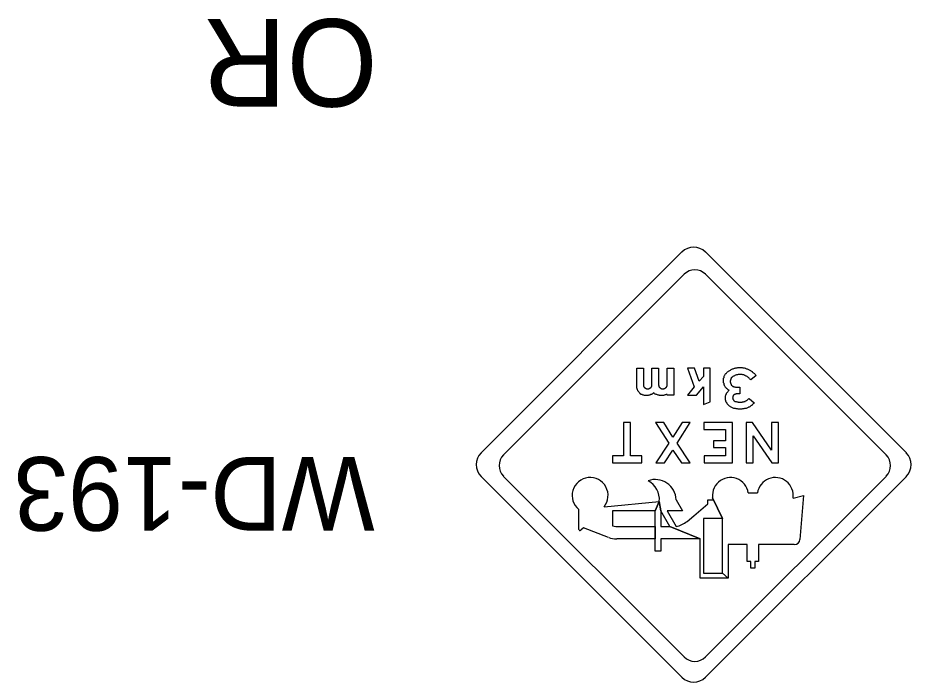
# Model space of a CAD drawing. Extents: x 1342 to 1558, y 178 to 457.
# Drawn here: x 1372.24 to 1398.65, y 386.57 to 406.21 of the extents above; entities that cross this region are included whole.
import ezdxf

# ---------------------------------------------------------------- set-up
doc = ezdxf.new("R2010")
doc.units = 0
for name, color, linetype in [('Level 1', 7, 'Continuous'), ('Level 10', 7, 'Continuous'), ('Level 44', 7, 'Continuous')]:
    doc.layers.add(name, color=color, linetype=linetype)

msp = doc.modelspace()

# ---------------------------------------------------------------- linework, layer by layer
at = {"layer": 'Level 1'}
for p, q in [((1393.832, 392.165), (1394.107, 392.165)), ((1389.57, 391.756), (1391.202, 391.916)), ((1391.202, 391.916), (1391.083, 391.633)), ((1391.083, 391.633), (1391.202, 391.916)), ((1391.248, 391.633), (1391.202, 391.916)), ((1391.202, 391.916), (1391.248, 391.633)), ((1391.703, 391.965), (1391.887, 391.633)), ((1392.642, 391.842), (1392.642, 391.965)), ((1392.642, 391.965), (1392.79, 391.965)), ((1393.076, 391.409), (1392.78, 392.016)), ((1392.78, 392.016), (1393.076, 391.409)), ((1395.158, 392.012), (1395.463, 392.09)), ((1395.463, 392.09), (1395.36, 390.791)), ((1388.826, 391.089), (1388.826, 391.676)), ((1391.083, 391.633), (1389.821, 391.633)), ((1389.821, 391.633), (1389.821, 391.194)), ((1391.083, 391.169), (1391.083, 391.633)), ((1391.513, 391.174), (1391.248, 391.633)), ((1391.248, 391.633), (1391.248, 391.169)), ((1391.887, 391.633), (1391.44, 391.633)), ((1391.44, 391.633), (1391.702, 391.177)), ((1392.221, 391.489), (1392.642, 391.842)), ((1392.025, 391.325), (1392.221, 391.489)), ((1393.076, 391.409), (1392.515, 391.409)), ((1392.515, 391.409), (1392.515, 389.793)), ((1393.076, 389.793), (1393.076, 391.409)), ((1388.962, 391.131), (1388.88, 391.064)), ((1389.707, 390.848), (1388.962, 391.131)), ((1390.011, 391.169), (1391.083, 391.169)), ((1391.083, 391.169), (1391.083, 390.804)), ((1391.083, 390.804), (1391.083, 391.169)), ((1391.248, 391.169), (1391.516, 391.169)), ((1392.41, 390.804), (1391.513, 391.174)), ((1391.513, 391.174), (1392.41, 390.804)), ((1391.516, 391.169), (1391.513, 391.174)), ((1391.083, 390.804), (1389.944, 390.804)), ((1391.083, 390.445), (1391.083, 390.804)), ((1392.41, 390.804), (1391.248, 390.804)), ((1391.248, 390.804), (1391.248, 390.445)), ((1392.41, 389.643), (1392.41, 390.804)), ((1393.804, 390.638), (1393.24, 390.638)), ((1393.24, 390.638), (1393.24, 389.643)), ((1393.804, 390.14), (1393.804, 390.638)), ((1395.194, 390.638), (1394.135, 390.638)), ((1394.135, 390.638), (1394.135, 390.14)), ((1391.248, 390.445), (1391.083, 390.445)), ((1393.907, 390.14), (1393.804, 390.14)), ((1393.907, 389.937), (1393.907, 390.14)), ((1394.135, 390.14), (1394.029, 390.14)), ((1394.029, 390.14), (1394.029, 389.937)), ((1392.515, 389.793), (1393.076, 389.793)), ((1393.24, 389.643), (1393.076, 389.793)), ((1393.076, 389.793), (1393.24, 389.643)), ((1394.029, 389.937), (1393.907, 389.937)), ((1393.24, 389.643), (1392.41, 389.643))]:
    msp.add_line(p, q, dxfattribs=at)
for points in [[(1390.54, 395.296), (1390.54, 395.85), (1390.738, 395.85), (1390.738, 395.361)], [(1390.982, 395.361), (1390.982, 395.85), (1391.179, 395.85), (1391.179, 395.361)], [(1391.433, 395.361), (1391.433, 395.85), (1391.631, 395.85), (1391.631, 395.051), (1391.433, 395.051), (1391.433, 395.079)], [(1392.506, 394.778), (1392.703, 394.854), (1392.703, 395.85), (1392.506, 395.85), (1392.506, 395.606), (1392.383, 395.465), (1392.242, 395.85), (1392.035, 395.85), (1392.233, 395.305), (1392.035, 395.051), (1392.308, 395.051), (1392.506, 395.305), (1392.506, 394.778)], [(1393.267, 395.202), (1393.249, 395.202), (1393.239, 395.211), (1393.23, 395.22), (1393.22, 395.23), (1393.211, 395.239), (1393.192, 395.249), (1393.183, 395.267), (1393.173, 395.277), (1393.164, 395.286), (1393.164, 395.296), (1393.154, 395.305), (1393.145, 395.324), (1393.136, 395.333), (1393.136, 395.352), (1393.126, 395.361), (1393.117, 395.371), (1393.117, 395.39), (1393.117, 395.399), (1393.107, 395.418), (1393.107, 395.427), (1393.107, 395.446), (1393.107, 395.465), (1393.107, 395.474), (1393.107, 395.493), (1393.107, 395.502), (1393.107, 395.521), (1393.107, 395.531), (1393.107, 395.549), (1393.107, 395.559), (1393.117, 395.578), (1393.117, 395.587), (1393.126, 395.606), (1393.126, 395.615), (1393.136, 395.634), (1393.145, 395.643), (1393.145, 395.653), (1393.154, 395.672), (1393.164, 395.681), (1393.173, 395.691), (1393.183, 395.7), (1393.192, 395.709), (1393.201, 395.728), (1393.211, 395.738), (1393.22, 395.747), (1393.239, 395.756), (1393.249, 395.766), (1393.267, 395.775), (1393.286, 395.784), (1393.305, 395.794), (1393.314, 395.804), (1393.333, 395.813), (1393.352, 395.822), (1393.371, 395.832), (1393.39, 395.832), (1393.408, 395.841), (1393.427, 395.85), (1393.446, 395.85), (1393.465, 395.86), (1393.483, 395.86), (1393.502, 395.86), (1393.521, 395.87), (1393.54, 395.87), (1393.559, 395.87), (1393.577, 395.87), (1393.597, 395.87), (1393.615, 395.87), (1393.634, 395.87), (1393.653, 395.87), (1393.672, 395.86), (1393.69, 395.86), (1393.709, 395.86), (1393.738, 395.85), (1393.756, 395.85), (1393.766, 395.841), (1393.784, 395.832), (1393.804, 395.832), (1393.822, 395.822), (1393.841, 395.813), (1393.86, 395.804), (1393.879, 395.794), (1393.897, 395.784), (1393.907, 395.775), (1393.925, 395.766), (1393.945, 395.756), (1393.954, 395.747), (1393.973, 395.728), (1393.991, 395.719), (1394.001, 395.709), (1394.02, 395.691), (1394.029, 395.681), (1394.039, 395.663), (1394.057, 395.643), (1394.066, 395.634)], [(1393.361, 395.587), (1393.352, 395.578), (1393.342, 395.578), (1393.333, 395.568), (1393.333, 395.559), (1393.324, 395.549), (1393.314, 395.54), (1393.314, 395.531), (1393.314, 395.521), (1393.305, 395.512), (1393.305, 395.502), (1393.305, 395.493), (1393.295, 395.484), (1393.295, 395.474), (1393.295, 395.465), (1393.295, 395.456), (1393.295, 395.446), (1393.295, 395.437), (1393.305, 395.427), (1393.305, 395.418), (1393.305, 395.408), (1393.314, 395.399), (1393.314, 395.39), (1393.324, 395.38), (1393.324, 395.371), (1393.333, 395.361), (1393.333, 395.352), (1393.342, 395.352), (1393.352, 395.343), (1393.361, 395.333), (1393.371, 395.333), (1393.371, 395.324), (1393.38, 395.315), (1393.39, 395.315), (1393.399, 395.315), (1393.408, 395.305), (1393.418, 395.305), (1393.427, 395.305), (1393.436, 395.305), (1393.456, 395.296), (1393.465, 395.296)], [(1393.907, 395.512), (1393.897, 395.521), (1393.879, 395.531), (1393.869, 395.54), (1393.86, 395.559), (1393.85, 395.568), (1393.841, 395.578), (1393.822, 395.587), (1393.813, 395.597), (1393.804, 395.606), (1393.784, 395.615), (1393.775, 395.615), (1393.756, 395.625), (1393.747, 395.634), (1393.728, 395.634), (1393.718, 395.643), (1393.7, 395.653), (1393.681, 395.653), (1393.672, 395.653), (1393.653, 395.663), (1393.634, 395.663), (1393.625, 395.663), (1393.606, 395.663), (1393.587, 395.663), (1393.577, 395.663), (1393.559, 395.663), (1393.54, 395.663), (1393.531, 395.663), (1393.512, 395.653), (1393.502, 395.653), (1393.483, 395.653), (1393.465, 395.643), (1393.456, 395.643), (1393.436, 395.634), (1393.427, 395.625), (1393.408, 395.615), (1393.399, 395.615), (1393.38, 395.606), (1393.371, 395.597), (1393.361, 395.587)], [(1394.066, 395.634), (1393.907, 395.512)], [(1390.738, 395.361), (1390.738, 395.352), (1390.738, 395.343), (1390.738, 395.333), (1390.738, 395.324), (1390.747, 395.315), (1390.747, 395.305), (1390.756, 395.296), (1390.756, 395.286), (1390.766, 395.277), (1390.775, 395.277), (1390.775, 395.267), (1390.784, 395.258), (1390.794, 395.258), (1390.803, 395.249), (1390.813, 395.249), (1390.822, 395.239), (1390.832, 395.239), (1390.841, 395.239), (1390.85, 395.239), (1390.859, 395.239), (1390.869, 395.239), (1390.879, 395.239), (1390.888, 395.239), (1390.897, 395.239), (1390.907, 395.249), (1390.916, 395.249), (1390.925, 395.258), (1390.935, 395.258), (1390.944, 395.267), (1390.944, 395.277), (1390.954, 395.277), (1390.963, 395.286), (1390.963, 395.296), (1390.973, 395.305), (1390.973, 395.315), (1390.982, 395.324), (1390.982, 395.333), (1390.982, 395.343), (1390.982, 395.352), (1390.982, 395.361)], [(1391.179, 395.361), (1391.179, 395.352), (1391.189, 395.343), (1391.189, 395.333), (1391.189, 395.324), (1391.189, 395.315), (1391.198, 395.305), (1391.198, 395.296), (1391.208, 395.286), (1391.217, 395.277), (1391.226, 395.267), (1391.236, 395.258), (1391.245, 395.249), (1391.255, 395.249), (1391.264, 395.249), (1391.273, 395.239), (1391.283, 395.239), (1391.292, 395.239), (1391.302, 395.239), (1391.311, 395.239), (1391.32, 395.239), (1391.33, 395.239), (1391.339, 395.239), (1391.349, 395.249), (1391.358, 395.249), (1391.368, 395.249), (1391.377, 395.258), (1391.386, 395.258), (1391.386, 395.267), (1391.396, 395.277), (1391.405, 395.277), (1391.405, 395.286), (1391.414, 395.296), (1391.414, 395.305), (1391.424, 395.305), (1391.424, 395.315), (1391.424, 395.324), (1391.433, 395.333), (1391.433, 395.343), (1391.433, 395.352), (1391.433, 395.361)], [(1391.038, 395.126), (1391.02, 395.117), (1391.01, 395.108), (1391.001, 395.098), (1390.991, 395.089), (1390.982, 395.089), (1390.973, 395.079), (1390.963, 395.07), (1390.944, 395.07), (1390.935, 395.061), (1390.925, 395.051), (1390.907, 395.051), (1390.897, 395.051), (1390.879, 395.042), (1390.869, 395.042), (1390.859, 395.042), (1390.841, 395.042), (1390.832, 395.042), (1390.813, 395.042), (1390.803, 395.042), (1390.784, 395.042), (1390.775, 395.042), (1390.766, 395.042), (1390.747, 395.051), (1390.738, 395.051), (1390.728, 395.051), (1390.709, 395.061), (1390.7, 395.07), (1390.69, 395.07), (1390.672, 395.079), (1390.662, 395.089), (1390.652, 395.089), (1390.643, 395.098), (1390.634, 395.108), (1390.625, 395.117), (1390.615, 395.126), (1390.606, 395.136), (1390.597, 395.154), (1390.587, 395.164), (1390.577, 395.173), (1390.568, 395.183), (1390.568, 395.192), (1390.559, 395.211), (1390.559, 395.22), (1390.549, 395.23), (1390.549, 395.249), (1390.54, 395.258), (1390.54, 395.267), (1390.54, 395.286), (1390.54, 395.296)], [(1391.433, 395.079), (1391.414, 395.07), (1391.405, 395.07), (1391.386, 395.061), (1391.377, 395.061), (1391.358, 395.051), (1391.349, 395.051), (1391.33, 395.042), (1391.32, 395.042), (1391.302, 395.042), (1391.283, 395.042), (1391.273, 395.042), (1391.255, 395.042), (1391.236, 395.042), (1391.226, 395.042), (1391.208, 395.042), (1391.198, 395.051), (1391.179, 395.051), (1391.17, 395.051), (1391.151, 395.061), (1391.132, 395.07), (1391.123, 395.07), (1391.114, 395.079), (1391.095, 395.089), (1391.085, 395.089), (1391.066, 395.098), (1391.057, 395.108), (1391.048, 395.117), (1391.038, 395.126)], [(1393.305, 394.713), (1393.295, 394.722), (1393.277, 394.731), (1393.267, 394.741), (1393.258, 394.75), (1393.249, 394.76), (1393.239, 394.769), (1393.23, 394.778), (1393.22, 394.788), (1393.211, 394.797), (1393.211, 394.816), (1393.201, 394.826), (1393.192, 394.835), (1393.183, 394.844), (1393.183, 394.863), (1393.173, 394.872), (1393.173, 394.891), (1393.173, 394.901), (1393.164, 394.91), (1393.164, 394.929), (1393.164, 394.938), (1393.164, 394.957), (1393.164, 394.967), (1393.164, 394.985), (1393.164, 394.995), (1393.164, 395.013), (1393.164, 395.023), (1393.164, 395.032), (1393.173, 395.051), (1393.173, 395.061), (1393.183, 395.079), (1393.183, 395.089), (1393.192, 395.098), (1393.192, 395.117), (1393.201, 395.126), (1393.211, 395.136), (1393.22, 395.145), (1393.23, 395.154), (1393.239, 395.173), (1393.249, 395.183), (1393.258, 395.192), (1393.267, 395.202)], [(1393.493, 395.098), (1393.483, 395.098), (1393.474, 395.098), (1393.465, 395.089), (1393.456, 395.089), (1393.446, 395.089), (1393.436, 395.079), (1393.427, 395.079), (1393.418, 395.07), (1393.408, 395.061), (1393.408, 395.051), (1393.399, 395.051), (1393.39, 395.042), (1393.39, 395.032), (1393.39, 395.023), (1393.38, 395.023), (1393.38, 395.013), (1393.38, 395.004), (1393.38, 394.995), (1393.38, 394.985), (1393.371, 394.976), (1393.38, 394.967), (1393.38, 394.957), (1393.38, 394.947), (1393.38, 394.938), (1393.39, 394.929), (1393.39, 394.92), (1393.399, 394.92), (1393.399, 394.91), (1393.408, 394.901), (1393.408, 394.891), (1393.418, 394.891), (1393.427, 394.882), (1393.436, 394.882), (1393.436, 394.872), (1393.446, 394.872)], [(1393.465, 395.296), (1393.587, 395.296), (1393.587, 395.098), (1393.493, 395.098)], [(1394.011, 394.826), (1394.001, 394.806), (1393.982, 394.797), (1393.973, 394.788), (1393.954, 394.769), (1393.945, 394.76), (1393.925, 394.75), (1393.907, 394.741), (1393.897, 394.731), (1393.879, 394.713), (1393.86, 394.703), (1393.841, 394.703), (1393.832, 394.694), (1393.813, 394.685), (1393.794, 394.675), (1393.775, 394.665), (1393.756, 394.665), (1393.738, 394.656), (1393.718, 394.656), (1393.7, 394.647), (1393.681, 394.647), (1393.663, 394.647), (1393.643, 394.637), (1393.625, 394.637), (1393.606, 394.637), (1393.587, 394.637), (1393.568, 394.637), (1393.549, 394.637), (1393.531, 394.637), (1393.512, 394.647), (1393.493, 394.647), (1393.474, 394.647), (1393.456, 394.656), (1393.446, 394.656), (1393.427, 394.665), (1393.408, 394.665), (1393.39, 394.675), (1393.371, 394.685), (1393.352, 394.694), (1393.333, 394.703), (1393.324, 394.703), (1393.305, 394.713)], [(1393.446, 394.872), (1393.465, 394.863), (1393.474, 394.863), (1393.493, 394.854), (1393.502, 394.854), (1393.521, 394.854), (1393.531, 394.844), (1393.549, 394.844), (1393.559, 394.844), (1393.577, 394.844), (1393.587, 394.844), (1393.606, 394.844), (1393.625, 394.844), (1393.634, 394.844), (1393.653, 394.844), (1393.663, 394.854), (1393.681, 394.854), (1393.69, 394.854), (1393.709, 394.863), (1393.718, 394.872), (1393.738, 394.872), (1393.747, 394.882), (1393.766, 394.891), (1393.775, 394.891), (1393.784, 394.901), (1393.804, 394.91), (1393.813, 394.92), (1393.822, 394.929), (1393.832, 394.938), (1393.841, 394.947), (1393.86, 394.957)], [(1393.86, 394.957), (1394.011, 394.826)], [(1390.691, 393.056), (1390.691, 393.263), (1390.353, 393.263), (1390.353, 394.251), (1390.146, 394.251), (1390.146, 393.263), (1389.817, 393.263), (1389.817, 393.056), (1390.691, 393.056)], [(1392.112, 393.056), (1391.736, 393.639), (1392.121, 394.251), (1391.877, 394.251), (1391.604, 393.809), (1391.341, 394.251), (1391.096, 394.251), (1391.482, 393.639), (1391.105, 393.056), (1391.36, 393.056), (1391.604, 393.432), (1391.858, 393.056), (1392.112, 393.056)], [(1393.372, 393.056), (1393.372, 394.251), (1392.516, 394.251), (1392.516, 394.044), (1393.165, 394.044), (1393.165, 393.705), (1392.808, 393.705), (1392.808, 393.507), (1393.165, 393.507), (1393.165, 393.263), (1392.535, 393.263), (1392.535, 393.056), (1393.372, 393.056)], [(1394.726, 393.056), (1394.726, 394.251), (1394.519, 394.251), (1394.519, 393.432), (1393.964, 394.251), (1393.777, 394.251), (1393.777, 393.056), (1393.984, 393.056), (1393.984, 393.855), (1394.529, 393.056), (1394.726, 393.056)]]:
    msp.add_lwpolyline(points, dxfattribs=at)
for centre, radius, start, end in [((1389.158, 392.09), 0.531, 320.9637, 231.3178), ((1391.084, 391.942), 0.619, 2.1917, 109.6612), ((1390.593, 391.981), 0.613, 353.8894, 62.4775), ((1393.306, 392.09), 0.531, 8.0405, 193.6001), ((1394.633, 392.09), 0.531, 351.5721, 171.9595), ((1388.859, 391.089), 0.0332, 180, 309.522), ((1390.011, 391.833), 0.664, 253.4264, 270), ((1391.599, 391.833), 0.664, 278.9934, 310.002), ((1389.944, 391.468), 0.664, 249.1426, 270), ((1395.195, 390.804), 0.166, 270, 355.4844)]:
    msp.add_arc(centre, radius, start, end, dxfattribs=at)
at = {"layer": 'Level 44'}
for p, q in [((1391.867, 399.289), (1385.938, 393.353)), ((1398.507, 393.353), (1392.569, 399.289)), ((1386.601, 393.288), (1391.939, 398.629)), ((1392.569, 398.629), (1397.914, 393.288)), ((1398.503, 393.353), (1398.507, 393.353)), ((1385.938, 392.649), (1391.867, 386.72)), ((1391.939, 387.317), (1386.601, 392.654)), ((1397.914, 392.654), (1392.569, 387.317)), ((1392.569, 386.72), (1398.507, 392.649))]:
    msp.add_line(p, q, dxfattribs=at)
for centre, radius, start, end in [((1392.22, 398.934), 0.497, 45, 135), ((1392.255, 398.311), 0.447, 45, 135), ((1386.287, 393.002), 0.497, 135, 225), ((1386.916, 392.972), 0.447, 135, 225), ((1397.594, 392.972), 0.447, 315, 45), ((1398.152, 393.002), 0.497, 315, 45), ((1392.255, 387.633), 0.447, 225, 315), ((1392.22, 387.07), 0.497, 225, 315)]:
    msp.add_arc(centre, radius, start, end, dxfattribs=at)

# ---------------------------------------------------------------- texts
at = {"layer": 'Level 10'}
for s, height, p in [('OR', 2.5849, (1382.874, 406.17)), ('WD-193', 2.177, (1382.791, 393.226))]:
    msp.add_text(s, height=height, rotation=180, dxfattribs=at).set_placement(p)

doc.saveas('drawing.dxf')
